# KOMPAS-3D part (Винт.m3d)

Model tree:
1. Эскиз:1
2. Операция выдавливания:1
     Расстояние 1 = 15; Расстояние 2 = 3
3. Эскиз:2
4. Операция выдавливания:2
     Расстояние 1 = 150; Расстояние 2 = 3
5. Эскиз:3
6. Операция выдавливания:3
     Расстояние 1 = 25; Расстояние 2 = 3
7. Условное изображение резьбы:1
     Длина резьбы = 150; Шаг резьбы = 5; Номинальный диаметр резьбы = 28
8. Эскиз:4
9. Эскиз:5
10. Смещенная плоскость:1
     Расстояние = 1
11. Эскиз:6
12. Плоскость через ребро и грань:1
13. Ось конической поверхности:1
14. Эскиз:7
15. Вырезать элемент вращения:1
     Угол 1 = 360
16. Эскиз:8
17. Операция вращения:1
     Угол 1 = 360
18. Проточка наружная Tr 28x5 ГОСТ 10549-80
19. Эскиз:9
20. Вырезать элемент выдавливания:1
     Расстояние 2 = 40; Расстояние 1 = 20.3167
21. Эскиз:10
22. Вырезать элемент выдавливания:2
     Расстояние 2 = 40; Расстояние 1 = 190
23. Фаска:1
     Угол = 3; Длина 1 = 4; Длина 2 = 0.209631
24. Фаска:2
     Угол = 45; Длина 1 = 0.5; Длина 2 = 0.5
25. Фаска:3
     Угол = 45; Длина 1 = 1; Длина 2 = 1
26. Эскиз:11
27. Вырезать элемент выдавливания:3  (labels: C:\Program Files (x86)\ASCON\KOMPAS-3D V12\Sys\vertical.lat; KTE.LIST=Du7ArA6Td4KLoATnVjMlQc; D1; R1)
     Расстояние 2 = 40; Расстояние 1 = 11.3581

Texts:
  KTE.LIST=Du7ArA6Td4KLoATnVjMlQc
  Edge1
  Edge2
